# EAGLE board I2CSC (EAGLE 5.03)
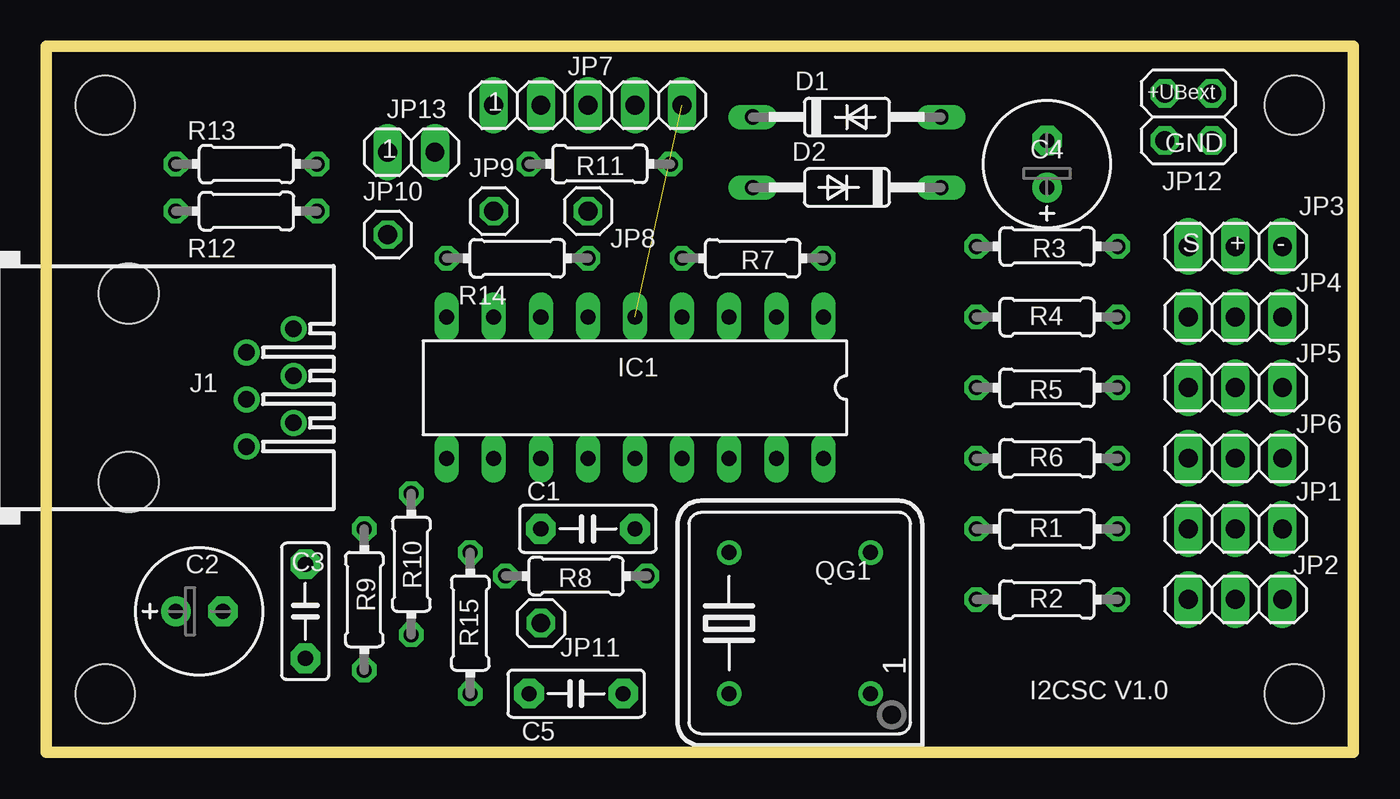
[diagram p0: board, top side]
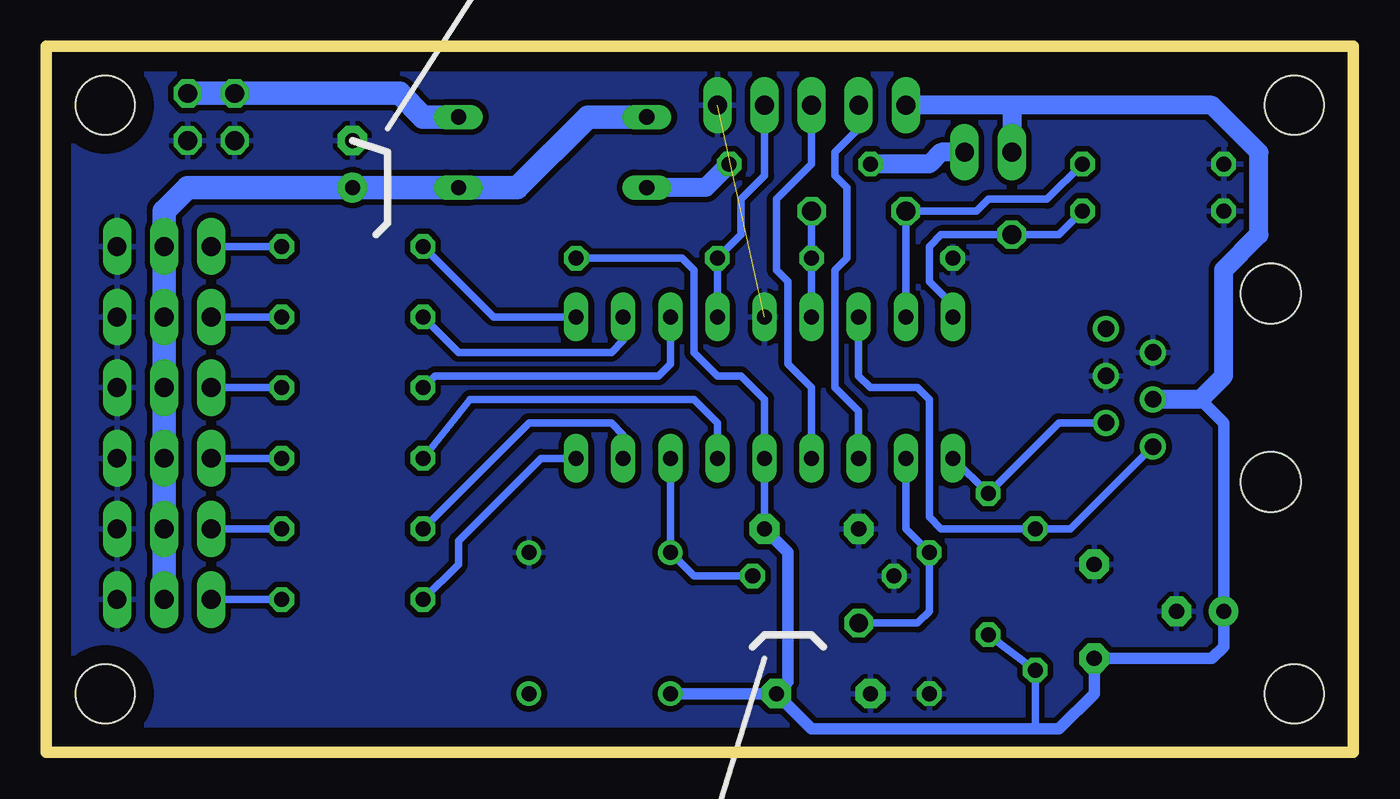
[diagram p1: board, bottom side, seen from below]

Size 70.48 x 38.1 mm. Coordinates in mm from the lower left corner, seen from the top.
Outline: 0,0 70.48,0 70.48,38.1 0,38.1 0,0
Copper layers (1*16): Top 0.035mm / dielectric 1.5mm / Bottom 0.035mm
Design rules "default": minimum track width 10mil, minimum drill 24mil, track to track 8mil, track to pad 8mil, pad to pad 8mil, via to via 8mil, smd to smd 8mil, copper to edge 40mil, drill to drill 8mil, minimum pad ring 10mil, minimum via ring 8mil, stop-mask expansion 4mil, vias tented up to drill 0mil, thermal gap 10mil
Holes 3.2 mm at 67.31,34.92 67.31,3.17 3.17,3.17 3.17,34.92

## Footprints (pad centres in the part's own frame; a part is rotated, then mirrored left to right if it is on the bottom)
C5B2.5 = drill 0.813 pad 1.6 octagon: 1 -2.54,0; 2 2.54,0
E2,5-7 = drill 0.813 pad 1.6 round: + -1.27,0 | drill 0.813 pad 1.6 octagon: - 1.27,0
DO35-10 = drill 0.813 long: A 5.08,0; C -5.08,0
DIL18 = drill 0.813 long: 1 -10.16,-3.81; 2 -7.62,-3.81; 3 -5.08,-3.81; 4 -2.54,-3.81; 5 0,-3.81; 6 2.54,-3.81; 7 5.08,-3.81; 8 7.62,-3.81; 9 10.16,-3.81; 10 10.16,3.81; 11 7.62,3.81; 12 5.08,3.81; 13 2.54,3.81; 14 0,3.81; 15 -2.54,3.81; 16 -5.08,3.81; 17 -7.62,3.81; 18 -10.16,3.81
520250-3 = drill 0.889 round: 1 -3.175,8.89; 2 -1.905,6.35; 3 -0.635,8.89; 4 0.635,6.35; 5 1.905,8.89; 6 3.175,6.35 | hole 3.251: -5.08,0; 5.08,0
1X03 = drill 1.016 long: 1 -2.54,0; 2 0,0; 3 2.54,0
1X05 = drill 1.016 long: 1 -5.08,0; 2 -2.54,0; 3 0,0; 4 2.54,0; 5 5.08,0
1X01 = drill 1.016 octagon: 1 0,0
2X02 = drill 1.016 octagon: 1 -1.27,-1.27; 2 -1.27,1.27; 3 1.27,-1.27; 4 1.27,1.27
1X02 = drill 1.016 long: 1 -1.27,0; 2 1.27,0
DIL08S = drill 0.813 round: 1 -3.81,-3.81; 4 3.81,-3.81; 5 3.81,3.81; 8 -3.81,3.81
0204/7 = drill 0.813 octagon: 1 -3.81,0; 2 3.81,0

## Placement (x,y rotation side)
C1  100n  [C5B2.5]  29.21,12.06 180 top
C2  220u/16V  [E2,5-7]  8.26,7.62 0 top
C3  100n  [C5B2.5]  13.97,7.62 90 top
C4  220u/16V  [E2,5-7]  53.98,31.75 90 top
C5  100n  [C5B2.5]  28.57,3.17 180 top
D1  SB140  [DO35-10]  43.18,34.29 0 top
D2  BAT85  [DO35-10]  43.18,30.48 180 top
IC1  PIC16F819  [DIL18]  31.75,19.68 180 top
J1  [520250-3]  4.45,19.68 270 top
JP1  [1X03]  64.14,12.06 0 top
JP2  [1X03]  64.14,8.26 0 top
JP3  [1X03]  64.14,27.3 0 top
JP4  [1X03]  64.14,23.5 0 top
JP5  [1X03]  64.14,19.68 0 top
JP6  [1X03]  64.14,15.88 0 top
JP7  [1X05]  29.21,34.92 0 top
JP8  [1X01]  29.21,29.21 0 top
JP9  [1X01]  24.13,29.21 0 top
JP10  [1X01]  18.41,27.94 0 top
JP11  [1X01]  26.67,6.99 0 top
JP12  [2X02]  61.59,34.29 270 top
JP13  [1X02]  19.68,32.38 0 top
QG1  [DIL08S]  40.64,6.99 90 top
R1  100  [0204/7]  53.98,12.06 0 top
R2  100  [0204/7]  53.98,8.26 0 top
R3  100  [0204/7]  53.98,27.3 0 top
R4  100  [0204/7]  53.98,23.5 0 top
R5  100  [0204/7]  53.98,19.68 0 top
R6  100  [0204/7]  53.98,15.88 0 top
R7  470k  [0204/7]  38.1,26.67 0 top
R8  470k  [0204/7]  28.57,9.53 0 top
R9  82k  [0204/7]  17.14,8.26 270 top
R10  82k  [0204/7]  19.68,10.16 270 top
R11  10E  [0204/7]  29.84,31.75 180 top
R12  470k  [0204/7]  10.79,29.21 0 top
R13  470k  [0204/7]  10.79,31.75 0 top
R14  470k  [0204/7]  25.4,26.67 0 top
R15  470k  [0204/7]  22.86,6.99 270 top

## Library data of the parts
C1 C3 C5 = capacitor-wima
C2 C4 = rcl
D1 D2 = diode
IC1 R1-R15 = Akki
J1 = con-amp
JP1-JP13 = pinhead
QG1 = crystal

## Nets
+5V: C1.1 C2.+ C3.1 C5.1 IC1.14 J1.4 JP7.1 JP13.1 QG1.8 R7.2 R9.2 R10.2
+UB: C4.+ D1.C D2.C JP1.2 JP2.2 JP3.2 JP4.2 JP5.2 JP6.2
GND: C1.2 C2.- C3.2 C4.- C5.2 IC1.5 J1.2 J1.3 JP1.3 JP2.3 JP3.3 JP4.3 JP5.3 JP6.3 JP7.5 JP12.3 JP12.4 QG1.4 R8.1 R12.1 R13.1 R14.1 R15.2
N$1: JP1.1 R1.2
N$2: JP2.1 R2.2
N$3: JP3.1 R3.2
N$4: JP4.1 R4.2
N$5: JP5.1 R5.2
N$6: JP6.1 R6.2
N$7: IC1.17 R1.1
N$8: IC1.18 R2.1
N$9: IC1.1 R3.1
N$10: IC1.2 R4.1
N$11: IC1.3 R5.1
N$12: IC1.15 R6.1
N$13: IC1.16 QG1.5 R8.2
N$14: IC1.4 JP7.4 R7.1
N$15: JP13.2 R11.2
N$16: IC1.6 JP8.1 R14.2
N$17: IC1.8 JP9.1 R13.2
N$18: IC1.12 JP7.2
N$19: IC1.13 JP7.3
N$20: IC1.9 JP10.1 R12.2
N$21: IC1.11 JP11.1 R15.1
N$22: D2.A R11.1
N$24: IC1.10 J1.5 R10.1
N$25: IC1.7 J1.6 R9.1
N$29: D1.A JP12.1 JP12.2

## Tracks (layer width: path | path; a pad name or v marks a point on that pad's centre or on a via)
+5V
  Bottom 0.406: C1.1 IC1.14 31.75,19.05 33.02,20.32 34.29,20.32 35.56,21.59 35.56,26.04 36.2,26.67 R7.2 | 17.14,1.27 R9.2 R10.2
  Bottom 0.61: 8.26,19.05 6.99,17.78 C2.+ 6.99,5.71 7.62,5.08 C3.1 13.97,3.17 15.88,1.27 17.14,1.27 29.21,1.27 C5.1 | C1.1 30.48,10.79 30.48,3.81 C5.1 | C5.1 QG1.8
  Bottom 1.016: J1.4 8.26,19.05 6.99,20.32 6.99,26.04 5.08,27.94 5.08,32.38 7.62,34.92 18.41,34.92 | 18.41,34.92 JP7.1 | 18.41,34.92 JP13.1
+UB
  Bottom 1.27: D1.C 41.27,34.29 45.09,30.48 D2.C C4.+ 62.87,30.48 64.14,29.21 JP3.2 JP4.2 JP5.2 JP6.2 JP1.2 JP2.2
GND  (1 unrouted)
  pour Bottom (isolate 0.305, rank 6): 0.64,37.47 0.64,0.64 69.85,0.64 69.85,37.47
N$1
  Bottom 0.406: R1.2 JP1.1
N$2
  Bottom 0.406: R2.2 JP2.1
N$3
  Bottom 0.406: R3.2 JP3.1
N$4
  Bottom 0.406: R4.2 JP4.1
N$5
  Bottom 0.406: R5.2 JP5.1
N$6
  Bottom 0.406: R6.2 JP6.1
N$7
  Bottom 0.406: IC1.17 39.37,17.14 40.01,17.78 44.45,17.78 R1.1
N$8
  Bottom 0.406: IC1.18 43.81,15.88 48.26,11.43 48.26,10.16 R2.1
N$9
  Bottom 0.406: IC1.1 46.35,23.5 R3.1
N$10
  Bottom 0.406: IC1.2 39.37,22.23 40.01,21.59 48.26,21.59 R4.1
N$11
  Bottom 0.406: IC1.3 36.83,20.95 37.47,20.32 49.53,20.32 R5.1
N$12
  Bottom 0.406: IC1.15 34.29,17.78 35.56,19.05 47.62,19.05 R6.1
N$13
  Bottom 0.406: IC1.16 QG1.5 35.56,9.53 R8.2
N$14
  Bottom 0.406: JP7.4 31.75,31.11 33.02,29.84 33.02,27.94 R7.1 IC1.4
N$15
  Bottom 1.016: JP13.2 22.23,32.38 22.86,31.75 R11.2
N$16
  Bottom 0.406: IC1.6 R14.2 JP8.1
N$17
  Bottom 0.406: R13.2 16.51,29.84 19.68,29.84 20.32,29.21 JP9.1 IC1.8
N$18
  Bottom 0.406: IC1.12 26.67,18.41 27.94,19.68 27.94,26.04 27.3,26.67 27.3,30.48 27.94,31.11 27.94,32.38 26.67,33.66 JP7.2
N$19
  Bottom 0.406: JP7.3 29.21,31.75 31.11,29.84 31.11,26.04 30.48,25.4 30.48,20.95 29.21,19.68 IC1.13
N$20
  Bottom 0.406: R12.2 15.88,27.94 JP10.1 22.23,27.94 22.86,27.3 22.86,25.4 21.59,24.13 IC1.9
N$21
  Bottom 0.406: IC1.11 24.13,12.06 R15.1 22.86,7.62 23.5,6.99 JP11.1
N$22
  Bottom 1.016: R11.1 34.92,30.48 D2.A
N$24
  Bottom 0.406: J1.5 15.88,17.78 R10.1 IC1.10
N$25
  Bottom 0.406: J1.6 15.24,12.06 R9.1 22.23,12.06 22.86,12.7 22.86,19.05 23.5,19.68 26.04,19.68 26.67,20.32 IC1.7
N$29
  Bottom 1.27: JP12.2 JP12.1 51.44,35.56 50.16,34.29 D1.A

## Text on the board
tPlace: 1 | +UBext | 1 | GND | S | + | - | I2CSC V1.0
bPlace: !!! | !!!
